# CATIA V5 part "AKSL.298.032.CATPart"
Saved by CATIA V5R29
Part number: АКСЛ.298.032
Definition: Уголок
Publications: "Грань по длине шипа", "Грань по ширине шипа"
Material "Steel": density 7860 kg/m3, Young's modulus 2e+11 Pa, Poisson ratio 0.266, thermal expansion 1.17e-05 1/K
Bounding box of the stored display mesh (mm): x -149 to 149, y -52 to 51, z -52 to 51
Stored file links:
  Z:\ООО Аксель\Соединения бруса\Соединения бруса\Соединения из листа\АКСЛ.298.030 (Трио)\AKSL.298.032.CATPart
  Z:\ООО Аксель\Соединения бруса\Соединения бруса\Соединения из листа\АКСЛ.298.030 (Трио)\AKSL.298.030.CATProduct
  Z:\ООО Аксель\Соединения бруса\Соединения бруса\Соединения из листа\АКСЛ.298.020 (Дуо)\AKSL.298.020.Skelet.CATPart
  Z:\#Catalog_GosNIIAS\Holes&Pockets\Part\Соединение шип-паз\Ship-Paz.CATPart
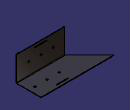
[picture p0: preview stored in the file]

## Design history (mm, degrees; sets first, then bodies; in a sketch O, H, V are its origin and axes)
External parameters (linked from other documents)
  `External.S металла` = 2 mm
  `External.R гиба` = 1.9 mm
  `External.K factor` = 0.49
SheetMetalParameters1: Thickness 2 {= `External.S металла`}, BendRadius 1.9 {= `External.R гиба`}, KFactor 0.49 {= `External.K factor`}, ReliefRadialLength 1, ReliefAxialLength 2, MinimumBendRadius 0
Set1
  DatumSurface1: linked copy from another document
  DatumCurve1: linked copy from another document
  Plane1: linked copy from another document
  DatumCurve2 to DatumCurve5: linked copy from another document
  Plane2: linked copy from another document
Body1 (main body)
  ThickSurface1: BotOffset 0, Surface DatumSurface1, TopOffset 2 {= `External.S металла`}
  Split1: SplitPlane Plane1
  Split2: SplitPlane Plane2
  Recognize1: Recognize_BendTable SheetMetalParameters1, Recognize_ReferenceFace face of ThickSurface1, Recognize_BendDefaultRadius 1.9 {= `External.R гиба`}, KFacteur 0.49 {= SheetMetalParameters1.KFactor}
  d_Bend1: Bend_BendTable SheetMetalParameters1, Bend_Thickness 2 {= `External.S металла`}, Bend_KFactor 0.49 {= SheetMetalParameters1.KFactor}, Bend_FirstSupport face of Recognize1, Bend_SecondSupport face of Recognize1, Bend_KFactorRadius 1.9 {= d_Bend1.CylindricalBendSurf_Radius}, Bend_Deduction -3.2761 {= (d_Bend1.CylindricalBendSurf_Radius+SheetMetalParameters1.Thickness*d_Bend1.Bend_KFactor)*(PI-abs(d_Bend1.BendSurf_OpenAngle))-2*(d_Bend1.CylindricalBendSurf_Radius+SheetMetalParameters1.Thickness)*tan(min((PI-abs(d_Bend1.BendSurf_OpenAngle)),(PI/2))/2)}
  Sketch1 on face of Recognize1, origin (117.977, 19.3948, -52), H (1, 0, 0), V (0, -1, 0)
    point P1 (6.023, 19.3948)
    construction line L1 (145.4124, 19.3948) -> (-179.5876, 19.3948)
    reference projected line E1 (-216.977, 19.3948) -> (83.023, 19.3948) from DatumCurve1
    construction line L2 (31.023, 97.3386) -> (31.023, -86.6614)
    reference projected line E2 (31.023, 71.3948) -> (31.023, -30.6052) from edge [face of Recognize1 | face of Recognize1]
    distance P1 L2 = 25
    horizontal: L1 H
    coincidence: E1 L1, P1 L1, E2 L2
    vertical: L2 V
  Hole1: placed by Sketch1, at (124, 0, -52) direction (0, 0, 1), diameter 8, through (limit type 6)
  RectPattern1: of Hole1, direction 1 instances 3, spacing 50, along edge [face of Recognize1 | face of d_Bend1] reversed
  Sketch2 on face of Recognize1, origin (105.1867, -52, 15.6921), H (1, 0, 0), V (0, 0, 1)
    point P1 (-6.1867, -15.6921)
    construction line L1 (-199.6909, -15.6921) -> (176.3091, -15.6921)
    reference projected line E1 (-204.1867, -15.6921) -> (95.8133, -15.6921) from DatumCurve1
    construction line L2 (43.8133, 59.7104) -> (43.8133, -123.2896)
    reference projected line E2 (43.8133, -67.6921) -> (43.8133, 36.3079) from edge [face of Recognize1 | face of Recognize1]
    distance P1 L2 = 50
    horizontal: L1 H
    coincidence: L1 E1, P1 L1, E2 L2
    vertical: L2 V
  Hole2: placed by Sketch2, at (99, -52, 0) direction (0, 1, 0), diameter 8, through (limit type 6)
  RectPattern2: of Hole2, direction 1 instances 3, spacing 50, along edge [face of Recognize1 | face of Recognize1] reversed
  Wall1: Thickness 2 {= `External.S металла`}, Profile Sketch3, ListTangentTo face of Recognize1, OffsetValue 0
  Sketch3 on face of Recognize1, origin (-52, 0, -52), H (0, -1, 0), V (-1, 0, 0)
    reference projected line E1 (-50, -201) -> (-50, 97) from edge [face of Recognize1 | face of Recognize1]
    line L1 (-51, 87) -> (-50, 87)
    line L2 (-50, 87) -> (-50, -191)
    line L3 (-50, -191) -> (-51, -191)
    line L4 (-51, -191) -> (-51, 87)
    axis line L5 (-50, -52) -> (-51, -52)
    point P7 (-50, -52)
    point P8 (-51, -52)
    distance L2 L4 = 1
    distance L1 L3 = 278
    length E1 = 298 (reference)
    perpendicularity: L2 L1
    midpoint: P7 L2, P8 L4, P7 E1
    coincidence: L2 E1
  Set2 "Шип в центре грани"
    Extract1 "Плоскость шипа": ExtractElem face of Wall1
    Extract2 "Грань по длине шипа": ExtractElem edge of Extract1
    Extract3 "Грань по ширине шипа": ExtractElem edge of Extract1
    Sketch4 on face of Recognize1, origin (0, -52, 0), H (1, 0, 0), V (0, 0, 1)
      reference projected line E1 (-47, -48.1) -> (-47, 52) from edge [face of Recognize1 | face of Recognize1]
      line L1 (149, 52) -> (149, 51)
      line L2 (149, 51) -> (139.5, 51)
      line L3 (139.5, 51) -> (139.5, 50)
      line L4 (139.5, 50) -> (-39.5, 50)
      line L5 (-39.5, 50) -> (-39.5, 51)
      line L6 (-39.5, 51) -> (-47, 51)
      point P12 (-47, 51)
      line L7 (-47, 51) -> (-47, 52)
      line L8 (-47, 52) -> (149, 52)
      distance L8 L2 = 1
      distance L8 L4 = 2
      distance L3 L1 = 9.5
      distance L7 L5 = 7.5
      distance L8 L6 = 1
      vertical: L1 V, L3 V, L5 V, L7 V
      horizontal: L2 H, L4 H, L6 H, L8 H
      coincidence: P12 E1
  CutOut1: Direction Sketch4, EndLimit through (limit type 2), Orientation true, Profile Sketch4, StartLimit through (limit type 2), Thickness1 2, Thickness2 2
  CutOut2: Direction Sketch5, EndLimit through (limit type 2), Orientation true, Profile Sketch5, StartLimit through (limit type 2)
  CutOut3: Direction Sketch6, EndLimit through (limit type 2), Orientation true, Profile Sketch6, StartLimit through (limit type 2)
  Sketch5 on DatumCurve2, origin (24.9612, -50, 40), H (1, 0, 0), V (0, 0, -1)
    reference projected line E1 (0, 0) -> (0, 3) from DatumCurve3
    reference projected line E2 (0, 0) -> (50, 0) from DatumCurve2
    construction line L1 (0, 1.5) -> (25, 1.5)
    point P5 (0, 1.5)
    point P6 (25, 1.5)
    axis line L2 (25, 0) -> (25, 7.3468)
    point P7 (25, 0)
    line L3 (50.1, 3.1) -> (50.1, -0.1)
    line L4 (50.1, -0.1) -> (-0.1, -0.1)
    line L5 (-0.1, -0.1) -> (-0.1, 3.1)
    line L6 (-0.1, 3.1) -> (50.1, 3.1)
    distance L5 E1 = 0.1
    distance E2 L4 = 0.1
    midpoint: P5 E1, P7 E2
    coincidence: L2 P6
    equidistance: L3 L5 P6, L4 L6 P6
    parallelism: L1 E2, L2 E1, L6 L4, L3 L5
  Sketch6 on DatumCurve4, origin (24.9612, 37, -50), H (1, 0, 0), V (0, -1, 0)
    reference projected line E1 (0, -3) -> (0, 0) from DatumCurve5
    reference projected line E2 (0, 0) -> (50, 0) from DatumCurve4
    construction line L1 (0, -1.5) -> (25, -1.5)
    point P5 (0, -1.5)
    point P6 (25, -1.5)
    axis line L2 (25, 0) -> (25, 7.3468)
    point P7 (25, 0)
    line L3 (50.1, -3.1) -> (50.1, 0.1)
    line L4 (50.1, 0.1) -> (-0.1, 0.1)
    line L5 (-0.1, 0.1) -> (-0.1, -3.1)
    line L6 (-0.1, -3.1) -> (50.1, -3.1)
    distance L5 E1 = 0.1
    distance E2 L4 = 0.1
    midpoint: P5 E1, P7 E2
    coincidence: L2 P6
    equidistance: L3 L5 P6, L4 L6 P6
    parallelism: L1 E2, L2 E1, L6 L4, L3 L5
